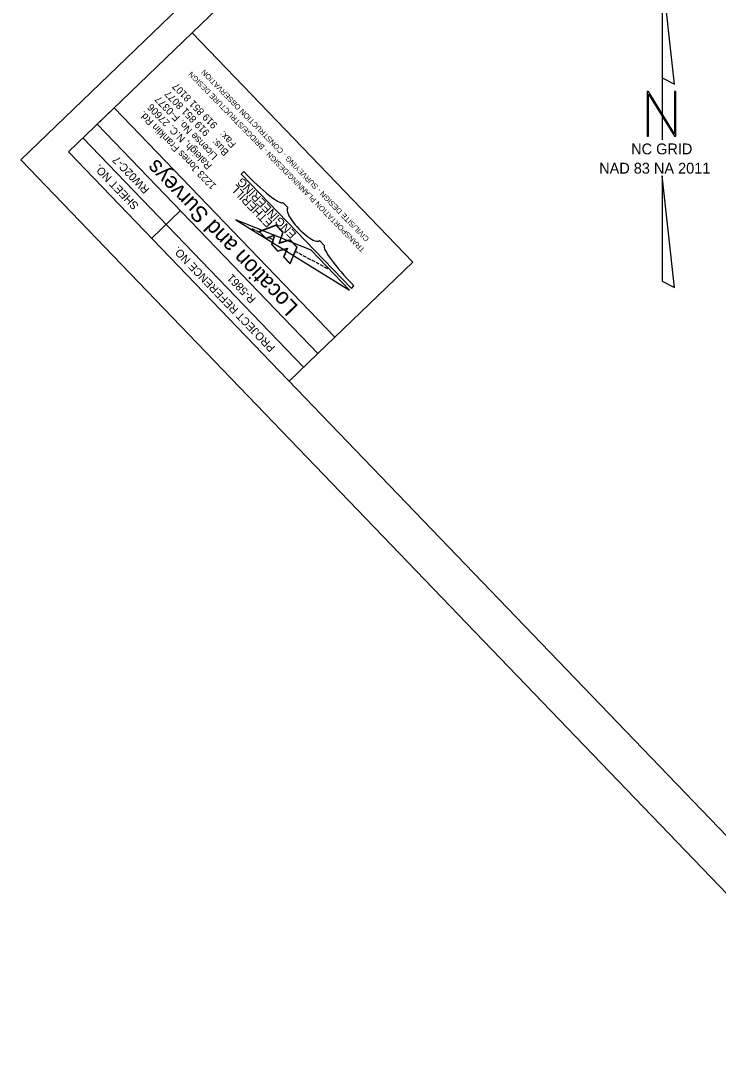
# Model space of a CAD drawing. Extents: x 471894 to 476235, y 503501 to 507878.
# Drawn here: x 471894 to 472859, y 504941 to 506381 of the extents above; entities that cross this region are included whole.
import ezdxf

# ---------------------------------------------------------------- set-up
doc = ezdxf.new("R2010")
doc.units = 0
for name, color, linetype in [('CTL North Arrow NAD 83 NA 2011 CELL', 7, 'Continuous'), ('CTL Sheet Border CELL', 7, 'Continuous'), ('CTL Sheet Notes CELL', 7, 'Continuous'), ('Sheet Plot Border Outside CELL', 7, 'Continuous')]:
    doc.layers.add(name, color=color, linetype=linetype)

msp = doc.modelspace()

# ---------------------------------------------------------------- linework, layer by layer
at = {"layer": 'CTL North Arrow NAD 83 NA 2011 CELL'}
msp.add_line((472782, 506229.8), (472782, 506229.8), dxfattribs=at)
for points in [[(472781.7, 506448.1), (472781.7, 506302.3), (472798.8, 506293.7)], [(472761.1, 506221.7), (472762.8, 506221.7), (472762.8, 506280), (472798.8, 506221.7), (472800.6, 506221.7), (472800.6, 506283.4), (472798.8, 506283.4), (472798.8, 506225.1), (472762.8, 506283.4), (472761.1, 506283.4)], [(472781.7, 506021), (472798.8, 506012.4), (472781.7, 506166.8)]]:
    msp.add_lwpolyline(points, close=True, dxfattribs=at)
msp.add_lwpolyline([(472781.7, 506302.3), (472781.7, 506216.5)], dxfattribs=at)
at = {"layer": 'CTL Sheet Border CELL'}
for p, q in [((472436.5, 506047.1), (472131.1, 506364.6)), ((471936.7, 506216), (471936.7, 506216)), ((471936.7, 506216), (471936.7, 506216)), ((472285.5, 505901.8), (471980, 506219.2)), ((471894, 506188.7), (471894, 506188.7)), ((472075.2, 506080.3), (472115.1, 506118.7)), ((472328.9, 505943.6), (472436.5, 506047.1)), ((472265.5, 505882.6), (472305.4, 505921))]:
    msp.add_line(p, q, dxfattribs=at)
for points in [[(471960, 506200), (474263.4, 503806.2), (475939, 505418.6), (473635.6, 507812.3)], [(472305.4, 505921), (471999.9, 506238.4), (472023.4, 506261), (472328.9, 505943.6)]]:
    msp.add_lwpolyline(points, close=True, dxfattribs=at)
at = {"layer": 'CTL Sheet Notes CELL'}
for p, q in [((472202.6, 506172.7), (472199, 506169.2)), ((472199, 506169.2), (472351.6, 506010.8)), ((472263.5, 506122.7), (472256.6, 506129.9)), ((472218.9, 506091.3), (472214.5, 506093.6)), ((472224.8, 506088.2), (472220.4, 506090.5)), ((472223.9, 506089.6), (472233.1, 506080)), ((472247.4, 506098.1), (472224.5, 506089.4)), ((472224.5, 506089.4), (472233.2, 506080.4)), ((472233.2, 506080.4), (472245.6, 506085.2)), ((472245.6, 506085.2), (472241.3, 506072)), ((472256.6, 506088.5), (472247.4, 506098.1)), ((472257, 506088.6), (472247.5, 506098.5)), ((472251.6, 506073.3), (472256.6, 506088.5)), ((472252.1, 506073.8), (472257, 506088.6)), ((472233.1, 506080), (472245.1, 506084.6)), ((472242.5, 506078.8), (472238, 506081.1)), ((472245.1, 506084.6), (472240.9, 506071.9)), ((472240.9, 506071.9), (472249.9, 506062.7)), ((472241.3, 506072), (472250, 506063)), ((472267, 506077.7), (472251.6, 506073.3)), ((472267.1, 506078.1), (472252.1, 506073.8)), ((472276.3, 506068.1), (472267, 506077.7)), ((472276.7, 506068.2), (472267.1, 506078.1)), ((472314.4, 506069.9), (472307.5, 506077.1)), ((472249.9, 506062.7), (472262.7, 506066.3)), ((472250, 506063), (472263.2, 506066.8)), ((472262.7, 506066.3), (472257.7, 506054.6)), ((472263.2, 506066.8), (472258.1, 506054.6)), ((472266.7, 506045.6), (472276.3, 506068.1)), ((472266.9, 506045), (472276.7, 506068.2)), ((472277.8, 506060), (472273.4, 506062.3)), ((472283.7, 506056.8), (472279.2, 506059.2)), ((472289.5, 506053.7), (472285.1, 506056.1)), ((472257.7, 506054.6), (472266.9, 506045)), ((472258.1, 506054.6), (472266.7, 506045.6)), ((472295.4, 506050.6), (472291, 506052.9)), ((472301.3, 506047.5), (472296.9, 506049.8)), ((472307.2, 506044.3), (472302.8, 506046.7)), ((472313.1, 506041.2), (472308.7, 506043.5)), ((472319, 506038.1), (472314.6, 506040.4)), ((472351.6, 506010.8), (472355.2, 506014.3))]:
    msp.add_line(p, q, dxfattribs=at)
msp.add_lwpolyline([(472349.2, 506008.5), (472296, 506063.7), (472191.7, 506105.8)], close=True, dxfattribs=at)
msp.add_lwpolyline([(472247.5, 506098.5), (472247.1, 506098.4), (472223.9, 506089.6)], dxfattribs=at)
for centre, major_axis, ratio, start_param, end_param in [((472209.2, 506179), (-47.4, 49.2), 0.134146, 1.570796, 3.141593), ((472285.5, 506099.9), (-22, 22.8), 0.289474, 0, 3.141593), ((472361.8, 506020.7), (47.4, -49.2), 0.134146, 3.141593, 4.712389)]:
    msp.add_ellipse(centre, major_axis=major_axis, ratio=ratio, start_param=start_param, end_param=end_param, dxfattribs=at)
at = {"layer": 'Sheet Plot Border Outside CELL'}
msp.add_lwpolyline([(476235.3, 505190.5), (473649.4, 507877.9), (471894, 506188.7), (474479.9, 503501.3)], close=True, dxfattribs=at)

# ---------------------------------------------------------------- texts
at = {"layer": 'CTL North Arrow NAD 83 NA 2011 CELL'}
for s, p in [('NC GRID', (472739, 506196.5)), ('NAD 83 NA 2011', (472694.7, 506169.8))]:
    msp.add_text(s, height=15, dxfattribs=at).set_placement(p)
at = {"layer": 'CTL Sheet Border CELL'}
for s, height, p in [('RW02C-7', 11.07, (472072.9, 506148.5)), ('Location and Surveys', 22.147, (472279.2, 505986)), ('SHEET NO.', 11.07, (472058, 506126.2)), ('PROJECT REFERENCE NO.', 11.074, (472246.9, 505929.5)), ('R-5861', 11.07, (472220.2, 505996.8))]:
    msp.add_text(s, height=height, rotation=133.8985, dxfattribs=at).set_placement(p)
at = {"layer": 'CTL Sheet Notes CELL'}
for s, height, rotation, p in [('TRANSPORTATION PLANNING/DESIGN - BRIDGE/STRUCTURE DESIGN', 7.333, 134.2745, (472370.9, 506065.3)), ('CIVIL/SITE DESIGN - SURVEYING - CONSTRUCTION OBSERVATION', 7.333, 134.2745, (472376.9, 506080.1)), ('Fax:   919 851 8107', 10, 134.2745, (472192.9, 506211.2)), ('License No. F-0377', 10, 134.2745, (472167, 506194.8)), ('Bus:   919 851 8077', 10, 134.2745, (472182.7, 506200.2)), ('Raleigh, N.C. 27606', 10, 134.2745, (472159.3, 506181.2)), ('1223 Jones Franklin Rd. ', 10, 134.2745, (472165.2, 506153.6)), ('ENGINEERING', 11.667, 133.9481, (472276.3, 506086.6)), ('ETHERILL', 11.67, 133.9481, (472243.5, 506102.1))]:
    msp.add_text(s, height=height, rotation=rotation, dxfattribs=at).set_placement(p)

doc.saveas('drawing.dxf')
